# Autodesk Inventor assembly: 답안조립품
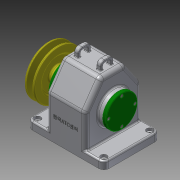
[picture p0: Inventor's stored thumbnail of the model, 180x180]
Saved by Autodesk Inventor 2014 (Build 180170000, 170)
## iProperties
Created: 2016-12
Part Number: 답안조립품
Document SubType Name: Assembly
Designer: USER
Author: USER
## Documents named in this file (15)
- C:\Users\USER\Desktop\461208V1022\답안조립품.iam
- C:\Users\USER\Desktop\461208V1022\본체.ipt
- C:\Users\USER\Desktop\461208V1022\축.ipt
- C:\Users\USER\Desktop\461208V1022\키 - 6 x 6 x 22.ipt
- C:\Users\USER\Desktop\461208V1022\V-벨트풀리.ipt
- C:\Users\USER\Desktop\461208V1022\뒤커버.ipt
- C:\Users\USER\Desktop\461208V1022\멈춤나사 - M4x10.ipt
- C:\Users\USER\Desktop\461208V1022\베어링 6203.ipt
- C:\Users\USER\Desktop\461208V1022\볼트 M3 x 8.ipt
- C:\Users\USER\Desktop\461208V1022\볼트 M3 x 10.ipt
- C:\Users\USER\Desktop\461208V1022\부시.ipt
- C:\Users\USER\Desktop\461208V1022\스퍼기어.ipt
- C:\Users\USER\Desktop\461208V1022\오일씰 28 40 8.ipt
- C:\Users\USER\Desktop\461208V1022\키 - 5 x 5 x 18.ipt
- C:\Users\USER\Desktop\461208V1022\앞커버.ipt
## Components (9 placed, 3 different names)
1. V-벨트풀리:1 — 각도:4
2. ISO 4762 M3 x 10:1
3. ISO 4762 M3 x 10:2
4. ISO 4762 M3 x 10:3
5. ISO 4762 M3 x 10:4
6. ISO 4762 M3 x 8:1
7. ISO 4762 M3 x 8:2
8. ISO 4762 M3 x 8:3
9. ISO 4762 M3 x 8:4
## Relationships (1: Angle 1)
- 각도:4 [Angle]: V-벨트풀리:1
